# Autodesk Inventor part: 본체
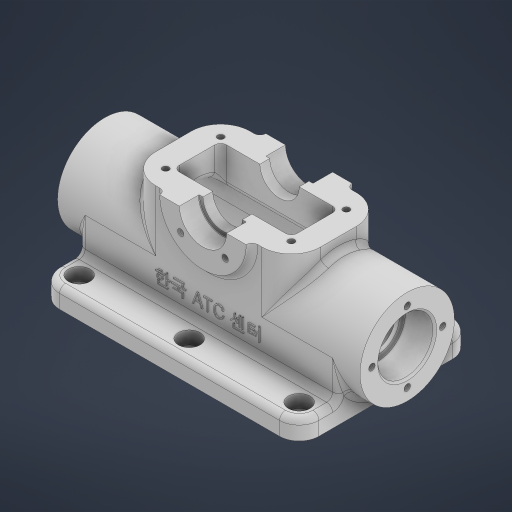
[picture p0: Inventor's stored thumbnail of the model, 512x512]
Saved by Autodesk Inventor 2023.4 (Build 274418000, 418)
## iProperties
Created: 2024-06
Part Number: 본체
Material: 알루미늄 6061
Document SubType Name: Modeling
Designer: Edu03
Density: 2.7 g/cm^3
Appearance: 기본값
Mass: 551.012 g
Surface Area: 614.152 cm^2
Volume: 204.079 cm^3
Author: Edu03
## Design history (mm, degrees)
sketch "스케치1"
  geometry: L1 (-94.718, 0)-(94.718, 0); L2 (-77, 24)-(-77, 14); L3 (-77, 14)-(-62, 14); L4 (-62, 14)-(-62, 11); L5 (-62, 11)-(-60, 11); L6 (-60, 11)-(-60, 18); L7 (-60, 18)-(60, 18); L8 (60, 18)-(60, 11); L9 (60, 11)-(62, 11); L10 (62, 11)-(62, 14); L11 (62, 14)-(77, 14); L12 (77, 14)-(77, 24); L13 (77, 24)-(-77, 24); 3 further points
  constraints: 26 end point, 9 perpendicular, 4 point on line, 2 midpoint, 1 coincident, 1 collinear, 1 horizontal, 1 vertical, 1 vertical alignment
  dimensions: "d0" = 154 distance of L12.end L2.start; "d1" = 15 distance of L2.end L3.end; "d2" = 15 distance of L10.end L11.end; "d3" = 120 distance of L6.end L7.end; "d4" = 48 diameter of L13 L1; "d5" = 22 diameter of L5 L1; "d6" = 28 diameter of L3 L1; "d7" = 6 distance between parallel lines of L13 L7
revolve "회전1" sketch "스케치1" stored, may be unused: angle "d8" = 90 deg
node "작업 평면1"
sketch "스케치2"
  geometry: L1 (44, -18)-(44, -28); L2 (44, -28)-(-44, -28); L3 (-44, -28)-(-44, -18); L4 (-24, -18)-(-24, 0); L5 (24, -18)-(24, 0); L6 (24, -18)-(44, -18); L7 (-44, -18)-(-24, -18); A1 r 24 centre (0, 0) between (-24, 0) and (24, 0) reference; 3 further points
  constraints: 14 end point, 3 parallel, 2 horizontal, 2 horizontal alignment, 2 perpendicular, 2 point on circle, 2 tangent, 2 vertical, 2 vertical alignment, 1 midpoint
  dimensions: "d10" = 88 distance of L1.end L2.end; "d12" = 28 distance from line of A1.centre L2; "d13" = 10 distance between parallel lines of L2 L6
extrude "돌출1" join sketch "스케치2" distance "d14" = 132; taper "d15" = 0 deg
node "작업 평면2"
sketch "스케치3"
  geometry: L1 (44, -28)-(-44, -28) reference; L2 (-18, -28)-(-18, 0); L3 (18, -28)-(18, 0); A1 r 18 centre (0, 0) between (18, 0) and (-18, 0) reference; 1 further point
  constraints: 4 end point, 2 point on circle, 2 point on line, 2 tangent, 2 vertical
extrude "돌출2" cut sketch "스케치3" distance "d17" = 120; taper "d18" = 0 deg
node "작업 평면3"
node "작업 평면4"
sketch "스케치5"
  geometry: L1 (24, 20)-(108, 20); L2 (108, 20)-(108, 68); L3 (108, 68)-(24, 68); L4 (24, 68)-(24, 20); L5 (143, 20)-(143, 68) reference; L6 (-11, 20)-(-11, 68) reference; L7 (0, 20)-(132, 20) reference; L8 (0, 20)-(0, 68) reference; L9 (0, 68)-(132, 68) reference; L10 (132, 68)-(132, 20) reference; 3 further points
  constraints: 8 end point, 2 midpoint, 2 parallel, 1 horizontal, 1 horizontal alignment, 1 perpendicular, 1 point on line, 1 vertical alignment
  dimensions: "d22" = 84 distance of L1.start L1.end
extrude "돌출3" join sketch "스케치5" stored distance "d24" = 120; taper "d25" = 0 deg
sketch "스케치6"
  geometry: L1 (36, -56)-(96, -56); L2 (96, -56)-(96, -32); L3 (96, -32)-(36, -32); L4 (36, -32)-(36, -56); L5 (36, -56)-(96, -32); L6 (96, -56)-(36, -32); 1 further point
  constraints: 12 end point, 2 midpoint, 2 parallel, 1 horizontal, 1 perpendicular
  dimensions: "d26" = 60 distance of L2.end L3.end; "d27" = 24 distance between parallel lines of L3 L1
extrude "돌출4" cut sketch "스케치6" extent not by distance; stored distance "d28" = 10; taper "d29" = 0 deg
sketch "스케치9"
  geometry: L1 (36, 49)-(96, 49) reference; C1 r 22 at (66, 49); 3 further points
  constraints: 1 centre point, 1 midpoint
  dimensions: "d37" = 44 diameter of C1
extrude "돌출5" join sketch "스케치9" distance "d38" = 3; taper "d39" = 0 deg
sketch "스케치11"
  geometry: A1 r 22 centre (66, 49) between (44, 49) and (88, 49) reference; 2 further points
  constraints: 1 coincident
hole "구멍2" sketch "스케치11" at (66, 49) diameter "d40" = 20; stored, may be unused: countersink angle "d44" = 90 deg, drill point angle "d46" = 0 deg; dims "d41" = 6, "d42" = 24, "d43" = 10, "d45" = 8
sketch "스케치12" dims "d47" = 32
  geometry: L1 (66, 49)-(54.686, 37.686); L2 (66, 49)-(66, 53.677); A1 r 12 centre (66, 49) between (54, 49) and (78, 49) reference; 2 further points
  constraints: 4 end point, 1 coincident, 1 vertical, 3 other
  dimensions: "d48" = 45 deg angle of L2 L1
hole "구멍3" sketch "스케치12" at (54.686, 37.686) diameter "d49" = 3.242; stored, may be unused: countersink angle "d53" = 90 deg, drill point angle "d55" = 118 deg; dims "d50" = 8, "d51" = 24, "d52" = 10, "d54" = 10
sketch "스케치13"
  geometry: L1 (34, -30)-(98, -30); L2 (98, -30)-(98, -58); L3 (98, -58)-(34, -58); L4 (34, -58)-(34, -30); L5 (54, -17)-(78, -17) reference; L6 (108, -20)-(108, -68) reference; 5 further points
  constraints: 8 end point, 4 midpoint, 2 parallel, 1 horizontal, 1 horizontal alignment, 1 perpendicular, 1 vertical alignment
  dimensions: "d56" = 28 distance of L1.end L2.end; "d57" = 64 distance of L1.start L1.end
hole "구멍4" sketch "스케치13" at (34, -58), (98, -58), (98, -30), (34, -30) diameter "d58" = 3.242; stored, may be unused: countersink angle "d62" = 90 deg, drill point angle "d64" = 118 deg; dims "d59" = 8, "d60" = 4, "d61" = 2, "d63" = 10
sketch "스케치14"
  geometry: A1 r 18 centre (0, 0) between (12, 13.416) and (-12, 13.416); A2 r 18 centre (0, 0) between (12, 13.416) and (-12, 13.416) reference; 2 further points
  constraints: 1 centre point, 1 coincident, 1 point on circle, 1 vertical alignment
  dimensions: "d65" = 36 diameter of A1
hole "구멍5" sketch "스케치14" at (0, 18) diameter "d66" = 3.242; stored, may be unused: countersink angle "d70" = 90 deg, drill point angle "d72" = 118 deg; dims "d67" = 8, "d68" = 4, "d69" = 2, "d71" = 10
sketch "스케치15" dims "d76" = 36
  geometry: 3 further points
  constraints: 2 vertical alignment, 1 coincident, 2 other
hole "구멍6" sketch "스케치15" at (0, 18) diameter "d77" = 3.242; stored, may be unused: countersink angle "d81" = 90 deg, drill point angle "d83" = 118 deg; dims "d78" = 8, "d79" = 4, "d80" = 2, "d82" = 10
fillet "모깎기1" dims "d87" = 3
fillet "모깎기2" dims "d88" = 3
sketch "스케치16"
  geometry: L1 (10, 10)-(122, 10); 2 further points
  constraints: 2 end point, 1 horizontal, 1 midpoint, 1 vertical alignment
  dimensions: "d89" = 112 distance of L1.start L1.end; "d90" = 34 distance from line of point (66, 44) L1
hole "구멍7" sketch "스케치16" at (10, 10), (66, 10), (122, 10) diameter "d91" = 6.6; stored, may be unused: countersink angle "d95" = 90 deg, drill point angle "d97" = 0 deg; dims "d92" = 8, "d93" = 11, "d94" = 6.6, "d96" = 8
fillet "모깎기3" dims "d98" = 10
fillet "모깎기4" dims "d99" = 3
sketch "스케치17"
  geometry: L1 (24, -28)-(14, -28) reference; 2 further points
  constraints: 1 vertical alignment, 1 other
  dimensions: "d100" = 20 distance from line of L1 point (-42, -8)
feature "엠보싱1" sketch "스케치17" dims "d101" = 0.5, "d102" = 0
fillet "모깎기5" dims "d103" = 3
fillet "모깎기6" dims "d104" = 3
fillet "모깎기7" dims "d105" = 15
fillet "모깎기8" dims "d106" = 3
chamfer "모따기1" distance "d107" = 1; stored, may be unused: second distance "d108" = 2, angle "d109" = 45 deg
fillet "모깎기9" dims "d110" = 0.3
fillet "모깎기10" dims "d111" = 3
node "솔리드1"
mirror "미러2"
mirror "미러3"
mirror "미러4"
mirror "미러5"
pattern_circular "원형 패턴1" dims angle "d74" = 360 deg
pattern_circular "원형 패턴2" dims angle "d85" = 360 deg
mirror "미러6"
node "투영된 루프2"
feature "A9D066F2-1C7D-4E18-AEED-F7BC21143FA4" dims "d49" = 3.242, "d50" = 8, "d51" = 24, "d52" = 10, "d53" = 90 deg, "d54" = 10, "d55" = 118 deg
other parameters: "d9" = -11, "d16" = -6, "d21" = -59
